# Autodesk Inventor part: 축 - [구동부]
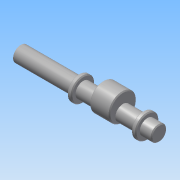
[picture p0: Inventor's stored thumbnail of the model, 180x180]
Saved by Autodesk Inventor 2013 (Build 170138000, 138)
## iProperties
Company: 한국ATC센터
Created: 2014-08
Part Number: 축 - [구동부]
Document SubType Name: Modeling
Designer: KYOUNG IL JANG
Density: 7.86 g/cm^3
Material: 강, 연강
Mass: 375.453 g
Surface Area: 117.379 cm^2
Volume: 47.7676 cm^3
Author: KYOUNG IL JANG
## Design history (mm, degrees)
sketch "스케치1"
  geometry: L1 (-76.5, 0)-(76.5, 0); L2 (-76.5, 0)-(-76.5, 8.5); L3 (-76.5, 8.5)-(-12.5, 8.5); L4 (-12.5, 8.5)-(-12.5, 13); L5 (-12.5, 13)-(-7.5, 13); L6 (-7.5, 13)-(-7.5, 8.5); L7 (-7.5, 8.5)-(58.5, 8.5); L8 (58.5, 8.5)-(58.5, 13); L9 (58.5, 13)-(63.5, 13); L10 (63.5, 13)-(63.5, 8.5); L11 (63.5, 8.5)-(76.5, 8.5); L12 (76.5, 8.5)-(76.5, 0); 2 further points
  constraints: 24 end point, 5 parallel, 1 coincident, 1 horizontal, 1 midpoint, 1 perpendicular
  dimensions: "d0" = 153 distance of L1.start L1.end (derived); "d2" = 17 diameter of L3 L1; "d3" = 26 diameter of L5 L1; "d4" = 17 diameter of L7 L1; "d5" = 26 diameter of L9 L1; "d6" = 17 diameter of L11 L1; "d7" = 5 distance of L8.end L9.end; "d8" = 5 distance of L4.end L5.end; "d10" = 64 distance of L2.end L3.end; "d11" = 13 distance of L10.end L11.end; "d35" = 66 distance between parallel lines of L8 L6
revolve "회전1" sketch "스케치1" stored, may be unused: angle "d12" = 90 deg
node "작업 평면1"
node "작업 평면2"
node "작업 평면4"
sketch "스케치6"
  geometry: C1 r 15 at (-5, -6); 1 further point
  constraints: 1 centre point, 1 horizontal alignment
  dimensions: "d31" = 30 diameter of C1; "d32" = 5 distance of C1.centre point (0, -6)
extrude "돌출4" join sketch "스케치6" stored distance "d33" = 22; taper "d34" = 0 deg
node "작업 평면3"
sketch "스케치5"
  geometry: L1 (32, 8.5)-(32, -8.5) reference; L2 (32, -2.5)-(14.5, -2.5); L3 (14.5, 2.5)-(32, 2.5); A1 r 2.5 centre (14.5, 0) between (14.5, 2.5) and (14.5, -2.5); 2 further points
  constraints: 4 end point, 2 point on circle, 2 point on line, 2 tangent, 1 centre point, 1 midpoint, 1 parallel, 1 perpendicular
  dimensions: "d23" = 5 distance between parallel lines of L3 L2; "d36" = 20 dimension on A1 L1
extrude "돌출3" cut sketch "스케치5" distance "d25" = 3; taper "d26" = 0 deg
chamfer "모따기1" distance "d27" = 1; stored, may be unused: second distance "d28" = 2, angle "d29" = 45 deg
node "솔리드1"
other parameters: "d13" = 9.5, "d18" = 9.5
